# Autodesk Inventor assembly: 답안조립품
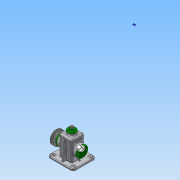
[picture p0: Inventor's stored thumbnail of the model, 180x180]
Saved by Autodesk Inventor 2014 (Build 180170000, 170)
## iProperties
Created: 2015-12
Part Number: 답안조립품
Document SubType Name: Assembly
Designer: Administrator
Author: Administrator
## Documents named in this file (19)
- D:\451225V1022\답안조립품.iam
- D:\451225V1022\1-본체.ipt
- D:\451225V1022\앞커버.ipt
- D:\451225V1022\오일실 15 25 7.ipt
- D:\451225V1022\와셔.ipt
- D:\451225V1022\키 5 x 5 x 14.ipt
- D:\451225V1022\편심축.ipt
- D:\451225V1022\V-벨트풀리.ipt
- D:\451225V1022\고정핀.ipt
- D:\451225V1022\뒤커버.ipt
- D:\451225V1022\링크.ipt
- D:\451225V1022\멈춤링 6 x 5.ipt
- D:\451225V1022\멈춤링 15 x 1.ipt
- D:\451225V1022\베어링 15 x 35 x 11.ipt
- D:\451225V1022\볼트 M3 x 8.ipt
- D:\451225V1022\볼트 M4 x 10.ipt
- D:\451225V1022\볼트 M6 x 12.ipt
- D:\451225V1022\상부부시.ipt
- D:\451225V1022\슬라이드바.ipt
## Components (16 placed, 6 different names)
1. 1-본체:1
2. V-벨트풀리:1 — 각도:2
3. 고정핀:1
4. ISO 4018 M6 x 12:1
5. ISO 4762 M4 x 10:1
6. ISO 4762 M4 x 10:2
7. ISO 4762 M4 x 10:3
8. ISO 4762 M4 x 10:4
9. ISO 4762 M4 x 10:5
10. ISO 4762 M4 x 10:6
11. ISO 4762 M4 x 10:7
12. ISO 4762 M4 x 10:8
13. ISO 4762 M3 x 8:1
14. ISO 4762 M3 x 8:2
15. ISO 4762 M3 x 8:3
16. ISO 4762 M3 x 8:4
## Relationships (1: Angle 1)
- 각도:2 [Angle]: V-벨트풀리:1
